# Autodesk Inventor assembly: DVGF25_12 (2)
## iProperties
Created: 2010-04
Part Number: DVGF25_12 (2)
Document SubType Name: Assembly
Designer: TB
Mass: 188.016 g
Surface Area: 589.582 cm^2
Volume: 188.016 cm^3
Density: 1 g/cm^3
Description: KM DVGF 25/12 - 100 mm
Slaglengde: 100.000 mm
Author: TB
